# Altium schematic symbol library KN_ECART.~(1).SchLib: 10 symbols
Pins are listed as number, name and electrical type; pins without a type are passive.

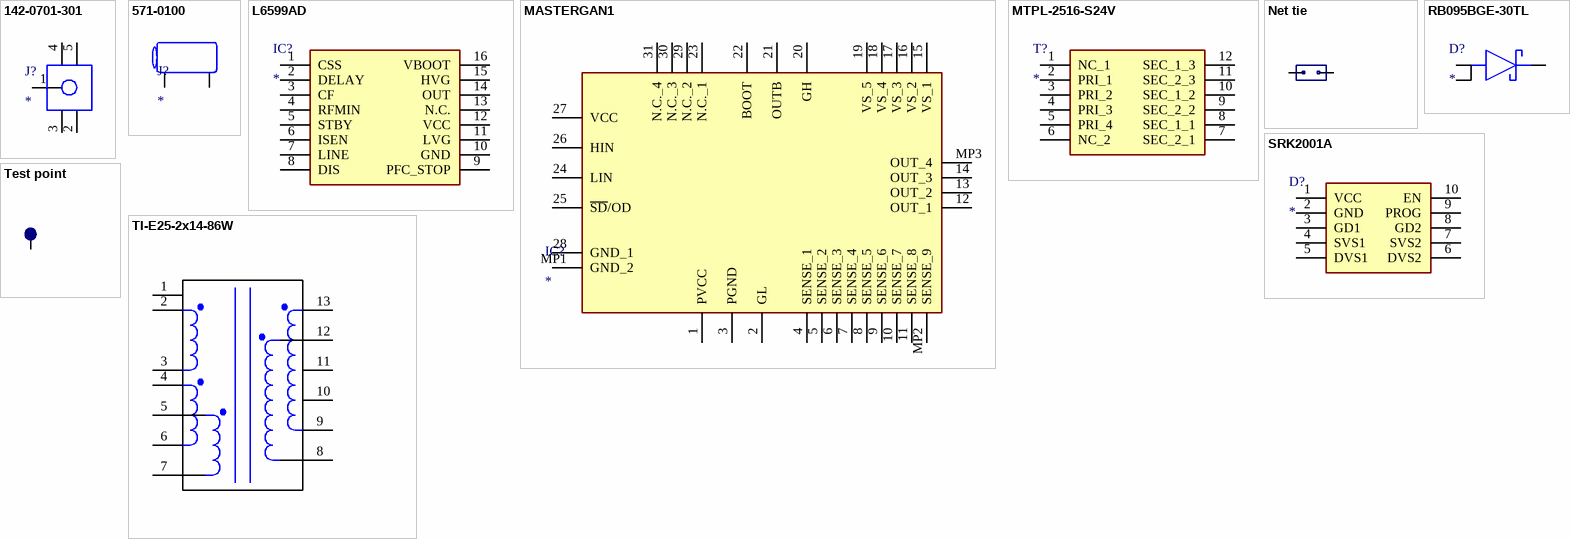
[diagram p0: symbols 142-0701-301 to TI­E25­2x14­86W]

## 142-0701-301
designator J?
Connector; Manufacturer_Name: Cinch Connectivity Solutions; Manufacturer_Part_Number: 142-0701-301
footprint 1420701301
pins: 1, 2, 3, 4, 5

## 571-0100
designator J?
Connector; Manufacturer_Name: DELTRON COMPONENTS; Manufacturer_Part_Number: 571-0100
footprint 5710100
pins: 1, 2 (power)

## L6599AD
designator IC?
Integrated Circuit; Manufacturer_Name: STMicroelectronics; Manufacturer_Part_Number: L6599AD
footprint SOIC127P600X175-16N
pins: 1 CSS, 2 DELAY, 3 CF, 4 RFMIN, 5 STBY, 6 ISEN, 7 LINE, 8 DIS, 9 PFC_STOP, 10 GND, 11 LVG, 12 VCC, 13 N.C., 14 OUT, 15 HVG, 16 VBOOT

## MASTERGAN1
designator IC?
Integrated Circuit; Manufacturer_Name: STMicroelectronics; Manufacturer_Part_Number: MASTERGAN1
footprint MASTERGAN1
pins: 1 PVCC, 2 GL, 3 PGND, 4 SENSE_1, 5 SENSE_2, 6 SENSE_3, 7 SENSE_4, 8 SENSE_5, 9 SENSE_6, 10 SENSE_7, 11 SENSE_8, 12 OUT_1, 13 OUT_2, 14 OUT_3, 15 VS_1, 16 VS_2, 17 VS_3, 18 VS_4, 19 VS_5, 20 GH, 21 OUTB, 22 BOOT, 23 N.C._1, 24 LIN, 25 ~{SD}/OD, 26 HIN, 27 VCC, 28 GND_1, 29 N.C._2, 30 N.C._3, 31 N.C._4, MP1 GND_2, MP2 SENSE_9, MP3 OUT_4

## MTPL-2516-S24V
designator T?
Transformer; Manufacturer_Name: Vishay; Manufacturer_Part_Number: MTPL-2516-S24V
footprint MTPL2516S24V
pins: 1 NC_1, 2 PRI_1, 3 PRI_2, 4 PRI_3, 5 PRI_4, 6 NC_2, 7 SEC_2_1, 8 SEC_1_1, 9 SEC_2_2, 10 SEC_1_2, 11 SEC_2_3, 12 SEC_1_3

## Net tie
designator NT?  (net tie, no BOM)
footprint Net tie (Net tie - SMD short)
pins: 1, 2

## RB095BGE-30TL
designator D?
Diode; Manufacturer_Name: ROHM Semiconductor; Manufacturer_Part_Number: RB095BGE-30TL
footprint RD3P175SNFRATL
pins: 1 A_1, 2 K, 3 A_2

## SRK2001A
designator D?
Diode; Manufacturer_Name: STMicroelectronics; Manufacturer_Part_Number: SRK2001A
footprint SOIC127P600X175-8N
pins: 1 VCC, 2 GND, 3 GD1, 4 SVS1, 5 DVS1, 6 DVS2, 7 SVS2, 8 GD2, 9 PROG, 10 EN

## Test point
designator TP?  (no BOM)
footprint Test point (Test point SMD, 50 mil)
pins: 1

## TI­E25­2x14­86W
designator L?
Transformer
footprint TI­E25­2x14­86W (tRANSFORMER)
pins: 1, 2, 3, 4, 5, 6, 7, 8, 9, 10, 11, 12, 13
